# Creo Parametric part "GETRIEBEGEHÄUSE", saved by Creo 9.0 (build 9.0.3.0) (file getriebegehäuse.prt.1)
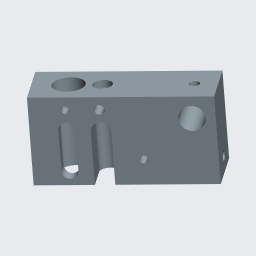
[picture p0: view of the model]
Units: millimeter Kilogram Sec (mmKs); MM, KILOGRAM, SECS
Materials in the file: STAHL

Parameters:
  SCHRAUBEN_GROESSE = "M4x.7"
  METRISCH = "JA"
  WERKSTOFF = "Stahl"
  ERSTELLER = "ARINDA"
  BENENNUNG = "XXX"
  TEILETYP = "K"
  PTC_MASTER_MATERIAL = "STAHL"

Other parameters: STEIGUNG, BOHR_DURCHM, GEWINDEDURCHMESSER, GEWINDEGÄNGE_PRO_INCH, GEWINDETIEFE, GEWINDELÄNGE, MASSE, ANSENKDURCHMESSER, ANSENKTIEFE, KEGELSENKER_DURCHMESSER, SENKWINKEL

Created from: KOPF.PRT

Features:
  1. coordinate system
  2. datum plane "RECHTS_Y-Z"
  3. datum plane "OBEN_X-Z"
  4. datum plane "VORNE_X-Y"
  5. datum axis
  6. datum axis
  7. datum axis
  8. datum point "PNT0"
  9. protrusion
  10. hole "Bohrung 1"
  11. hole "Bohrung 2"
  12. hole "Bohrung 3"
  13. hole "Bohrung 4"
  14. hole "Bohrung 5"
  15. hole "Bohrung 6"
  16. hole "Bohrung 7"
  17. extruded cut "Profil 2"
  18. hole "Bohrung 8"
  19. extruded cut "Profil 3"
  20. extruded cut "Profil 4"
  21. hole "Bohrung 9"

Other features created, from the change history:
  planar section "A"

Other named items: GRUNDKÖRPER, STÄNDERBOHRUNG, FIXIERUNG_STÄNDER, UMLENKROLLE, FIXIERUNG_UMLENKROLLE, SPINDEL, FIXIERUNG_SPINDELLAGER, FÜHRUNG_RIEMENSCHEIBE, FENSTER_SPINDEL, FEDERBOHRUNG, FEDERFENSTER, FEDERAUFHÄNGUNG, HEBELBOHRUNG, A_X, A_Y, A_Z, CS0

Layers: 01_ACHSEN, 01_ACHSEN_STD, 01_EBENEN_STD, 01_KOORDSYS_STD, 01_PUNKTE_STD, GEWINDE, SAMMELFLÄCHEN, VOLUMENGEOMETRIE

Notes: M4x.7 | GEWINDEBOHREN | 7.920 |  BOHREN (  | 3.300 | DURCH |   -(  |  ) BOHRUNG | M3x.5 | GEWINDEBOHREN | 6.000 |  BOHREN (  | 2.500 | DURCH |   -(  |  ) BOHRUNG | M3x.5 | GEWINDEBOHREN | DURCH |  BOHREN (  | 2.500 | DURCH |   -(  |  ) BOHRUNG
